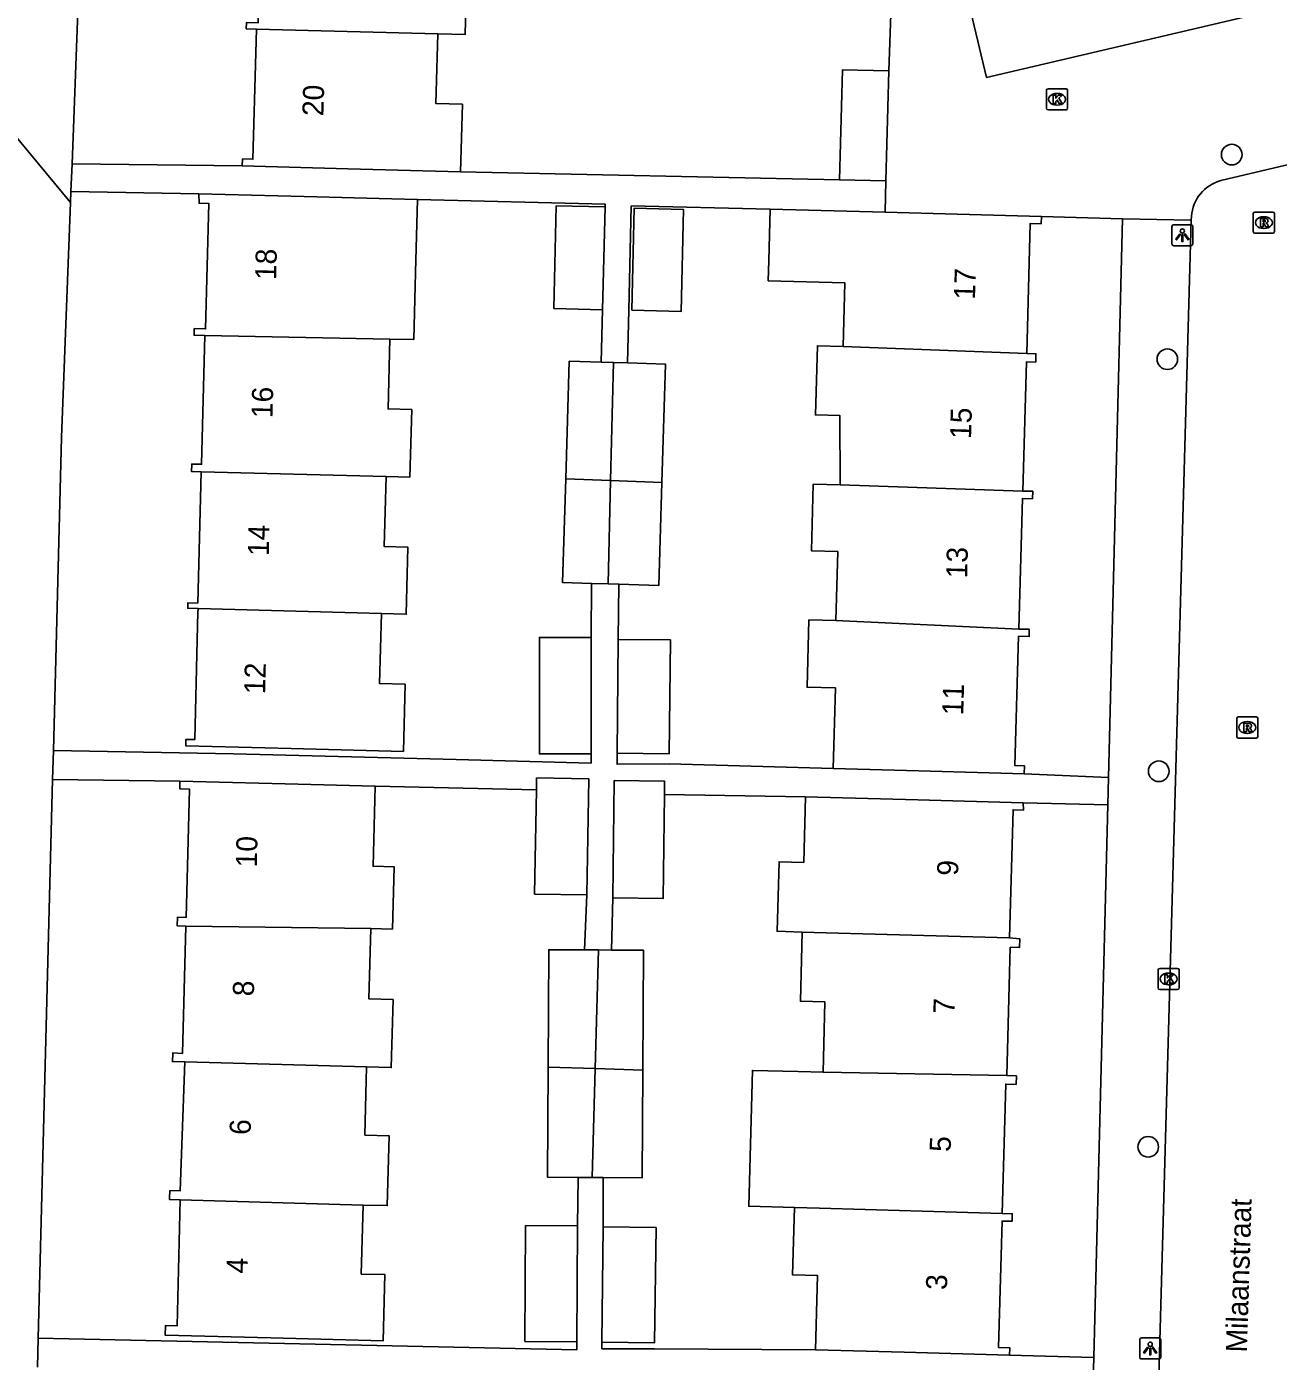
# Model space of a CAD drawing. Extents: x 162082 to 163393, y 388091 to 388632.
# Drawn here: x 162919.7 to 162979.1, y 388129.3 to 388192.6 of the extents above; entities that cross this region are included whole.
import ezdxf

# ---------------------------------------------------------------- set-up
doc = ezdxf.new("R2010")
doc.units = 0
for name, color, linetype in [('IMGEO_Boom', 7, 'Continuous'), ('IMGEO_Kolk', 7, 'Continuous'), ('IMGEO_Lichtpunt', 7, 'Continuous'), ('IMGEO_Openbare_ruimte_label', 7, 'Continuous'), ('IMGEO_Pand', 7, 'Continuous'), ('IMGEO_Pand_nummerreeks', 7, 'Continuous'), ('IMGEO_Rijbaan_lokaal_open', 7, 'Continuous'), ('IMGEO_Rioolput', 7, 'Continuous'), ('IMGEO_Voetpad_open', 7, 'Continuous')]:
    doc.layers.add(name, color=color, linetype=linetype)

msp = doc.modelspace()

# ---------------------------------------------------------------- linework, layer by layer
at = {"layer": 'IMGEO_Boom'}
for centre in [(162976.877, 388186.501), (162973.822, 388176.796), (162973.415, 388157.251), (162972.915, 388139.439)]:
    msp.add_circle(centre, 0.489, dxfattribs=at)
at = {"layer": 'IMGEO_Kolk'}
for p, q in [((162968.091, 388188.7), (162968.091, 388189.552)), ((162968.166, 388189.626), (162969.018, 388189.626)), ((162969.092, 388189.552), (162969.092, 388188.7)), ((162968.602, 388188.846), (162968.577, 388188.846)), ((162968.579, 388189.406), (162968.604, 388189.406)), ((162969.018, 388188.626), (162968.166, 388188.626)), ((162973.383, 388146.973), (162973.383, 388147.825)), ((162973.458, 388147.899), (162974.31, 388147.899)), ((162974.384, 388147.825), (162974.384, 388146.973)), ((162973.894, 388147.119), (162973.869, 388147.119)), ((162973.871, 388147.679), (162973.896, 388147.679)), ((162974.31, 388146.899), (162973.458, 388146.899))]:
    msp.add_line(p, q, dxfattribs=at)
for points in [[(162968.091, 388188.7), (162968.091, 388189.552)], [(162968.166, 388189.626), (162969.018, 388189.626)], [(162969.092, 388189.552), (162969.092, 388188.7)], [(162968.412, 388189.326), (162968.535, 388189.326), (162968.535, 388189.175), (162968.665, 388189.326), (162968.829, 388189.326), (162968.683, 388189.175), (162968.836, 388188.926), (162968.684, 388188.926), (162968.599, 388189.09), (162968.535, 388189.023), (162968.535, 388188.926), (162968.412, 388188.926), (162968.412, 388189.326)], [(162969.018, 388188.626), (162968.166, 388188.626)], [(162973.383, 388146.973), (162973.383, 388147.825)], [(162973.458, 388147.899), (162974.31, 388147.899)], [(162974.384, 388147.825), (162974.384, 388146.973)], [(162973.704, 388147.599), (162973.827, 388147.599), (162973.827, 388147.448), (162973.957, 388147.599), (162974.121, 388147.599), (162973.975, 388147.448), (162974.128, 388147.199), (162973.976, 388147.199), (162973.891, 388147.363), (162973.827, 388147.296), (162973.827, 388147.199), (162973.704, 388147.199), (162973.704, 388147.599)], [(162974.31, 388146.899), (162973.458, 388146.899)]]:
    msp.add_lwpolyline(points, dxfattribs=at)
for centre, start, end in [((162968.168, 388189.55), 91.55205, 178.44795), ((162968.168, 388189.55), 91.55205, 178.44795), ((162969.016, 388189.55), 1.55205, 88.44795), ((162969.016, 388189.55), 1.55205, 88.44795), ((162968.168, 388188.702), 181.55205, 268.44795), ((162968.168, 388188.702), 181.55205, 268.44795), ((162969.016, 388188.702), 271.55205, 358.44795), ((162969.016, 388188.702), 271.55205, 358.44795), ((162973.46, 388147.823), 91.55205, 178.44795), ((162973.46, 388147.823), 91.55205, 178.44795), ((162974.308, 388147.823), 1.55205, 88.44795), ((162974.308, 388147.823), 1.55205, 88.44795), ((162973.46, 388146.975), 181.55205, 268.44795), ((162973.46, 388146.975), 181.55205, 268.44795), ((162974.308, 388146.975), 271.55205, 358.44795), ((162974.308, 388146.975), 271.55205, 358.44795)]:
    msp.add_arc(centre, 0.0765, start, end, dxfattribs=at)
for centre, major_axis, ratio, start_param, end_param in [((162968.578, 388189.126), (-0.387, 0.002), 0.722429, 4.712389, 7.853982), ((162968.603, 388189.126), (-0.39, 0.002), 0.717154, 1.570796, 4.712389), ((162973.87, 388147.399), (-0.387, 0.002), 0.722429, 4.712389, 7.853982), ((162973.895, 388147.399), (-0.39, 0.002), 0.717154, 1.570796, 4.712389)]:
    msp.add_ellipse(centre, major_axis=major_axis, ratio=ratio, start_param=start_param, end_param=end_param, dxfattribs=at)
at = {"layer": 'IMGEO_Lichtpunt'}
for p, q in [((162974.938, 388183.177), (162974.13, 388183.177)), ((162974.938, 388183.177), (162974.13, 388183.177)), ((162974.036, 388183.082), (162974.036, 388182.275)), ((162974.036, 388183.082), (162974.036, 388182.275)), ((162975.032, 388182.275), (162975.032, 388183.082)), ((162975.032, 388182.275), (162975.032, 388183.082)), ((162974.13, 388182.181), (162974.938, 388182.181)), ((162974.13, 388182.181), (162974.938, 388182.181)), ((162972.511, 388130.275), (162972.511, 388129.468)), ((162972.511, 388130.275), (162972.511, 388129.468)), ((162973.413, 388130.37), (162972.605, 388130.37)), ((162973.413, 388130.37), (162972.605, 388130.37)), ((162973.507, 388129.468), (162973.507, 388130.275)), ((162973.507, 388129.468), (162973.507, 388130.275)), ((162972.605, 388129.374), (162973.413, 388129.374)), ((162972.605, 388129.374), (162973.413, 388129.374))]:
    msp.add_line(p, q, dxfattribs=at)
for points in [[(162974.41, 388182.746), (162974.449, 388182.718), (162974.261, 388182.456), (162974.223, 388182.483), (162974.41, 388182.746)], [(162974.512, 388182.698), (162974.559, 388182.698), (162974.559, 388182.376), (162974.512, 388182.376), (162974.512, 388182.698)], [(162974.622, 388182.718), (162974.66, 388182.745), (162974.847, 388182.483), (162974.808, 388182.455), (162974.622, 388182.718)], [(162972.885, 388129.939), (162972.924, 388129.911), (162972.736, 388129.649), (162972.698, 388129.676), (162972.885, 388129.939)], [(162972.987, 388129.891), (162973.034, 388129.891), (162973.034, 388129.569), (162972.987, 388129.569), (162972.987, 388129.891)], [(162973.097, 388129.911), (162973.135, 388129.938), (162973.322, 388129.676), (162973.283, 388129.648), (162973.097, 388129.911)]]:
    msp.add_lwpolyline(points, dxfattribs=at)
for centre in [(162974.535, 388182.88), (162973.01, 388130.073)]:
    msp.add_circle(centre, 0.0994, dxfattribs=at)
for centre, start, end in [((162974.13, 388183.082), 90, 180), ((162974.13, 388183.082), 90, 180), ((162974.938, 388183.082), 0, 90), ((162974.938, 388183.082), 0, 90), ((162974.13, 388182.275), 180, 270), ((162974.13, 388182.275), 180, 270), ((162974.938, 388182.275), 270, 0), ((162974.938, 388182.275), 270, 360), ((162972.605, 388130.275), 90, 180), ((162972.605, 388130.275), 90, 180), ((162973.413, 388130.275), 0, 90), ((162973.413, 388130.275), 0, 90), ((162972.605, 388129.468), 180, 270), ((162972.605, 388129.468), 180, 270), ((162973.413, 388129.468), 270, 0), ((162973.413, 388129.468), 270, 360)]:
    msp.add_arc(centre, 0.0946, start, end, dxfattribs=at)
at = {"layer": 'IMGEO_Pand'}
for points in [[(162930.625, 388192.454), (162930.137, 388192.468), (162930.145, 388192.767), (162930.711, 388192.752), (162930.879, 388198.904)], [(162939.348, 388198.681), (162939.259, 388195.428), (162940.603, 388195.392), (162940.516, 388192.195), (162939.221, 388192.23)], [(162929.952, 388185.968), (162929.961, 388186.297), (162930.456, 388186.283), (162930.625, 388192.454)], [(162939.221, 388192.23), (162930.625, 388192.454)], [(162939.221, 388192.23), (162939.13, 388188.925), (162940.388, 388188.891), (162940.3, 388185.684)], [(162958.276, 388185.312), (162958.42, 388190.53), (162960.619, 388190.469)], [(162960.619, 388190.469), (162960.475, 388185.252)], [(162929.952, 388185.968), (162934.951, 388185.831), (162940.3, 388185.684)], [(162958.276, 388185.312), (162960.475, 388185.252)], [(162928.181, 388177.916), (162927.665, 388177.93), (162927.673, 388178.25), (162928.213, 388178.236), (162928.369, 388184.179), (162927.902, 388184.191), (162927.892, 388184.644)], [(162938.256, 388184.372), (162937.039, 388184.404), (162932.891, 388184.513), (162927.892, 388184.644)], [(162938.256, 388184.372), (162938.165, 388180.911), (162938.082, 388177.726), (162936.956, 388177.755)], [(162947.038, 388179.14), (162944.726, 388179.195), (162944.843, 388184.079), (162947.154, 388184.024)], [(162947.038, 388179.14), (162947.154, 388184.024)], [(162948.419, 388179.121), (162948.534, 388183.953), (162950.88, 388183.897), (162950.765, 388179.066), (162948.419, 388179.121)], [(162958.448, 388177.401), (162958.531, 388180.416), (162954.896, 388180.516), (162954.922, 388181.481), (162954.989, 388183.92)], [(162960.434, 388183.77), (162954.989, 388183.92)], [(162960.434, 388183.77), (162967.851, 388183.566)], [(162967.851, 388183.566), (162967.841, 388183.222), (162967.321, 388183.237), (162967.152, 388177.071)], [(162928, 388171.451), (162927.546, 388171.463), (162927.555, 388171.824), (162928.021, 388171.812), (162928.181, 388177.916)], [(162936.956, 388177.755), (162928.181, 388177.916)], [(162936.956, 388177.755), (162936.869, 388174.435), (162937.987, 388174.406), (162937.903, 388171.209), (162936.772, 388171.239)], [(162958.3, 388170.839), (162958.296, 388174.125), (162957.134, 388174.157), (162957.225, 388177.435), (162958.448, 388177.401)], [(162958.448, 388177.401), (162967.152, 388177.071)], [(162967.152, 388177.071), (162967.59, 388177.059), (162967.579, 388176.659), (162967.142, 388176.671), (162966.973, 388170.545)], [(162945.288, 388171.117), (162945.456, 388176.701), (162946.972, 388176.655)], [(162947.55, 388176.638), (162946.972, 388176.655)], [(162947.419, 388171.037), (162947.55, 388176.638)], [(162948.22, 388176.618), (162947.55, 388176.638)], [(162948.22, 388176.618), (162950.021, 388176.564), (162949.851, 388170.945)], [(162927.853, 388164.971), (162927.364, 388164.985), (162927.371, 388165.244), (162927.837, 388165.232), (162928, 388171.451)], [(162936.772, 388171.239), (162928, 388171.451)], [(162936.772, 388171.239), (162936.685, 388167.91), (162937.807, 388167.88), (162937.724, 388164.699), (162936.548, 388164.73)], [(162946.52, 388166.162), (162945.139, 388166.203), (162945.288, 388171.117)], [(162947.419, 388171.037), (162945.288, 388171.117)], [(162947.419, 388171.037), (162947.305, 388166.138)], [(162949.851, 388170.945), (162947.419, 388171.037)], [(162949.851, 388170.945), (162949.704, 388166.065), (162947.807, 388166.123)], [(162958.099, 388164.397), (162958.189, 388167.674), (162956.939, 388167.708), (162957.026, 388170.874), (162958.3, 388170.839)], [(162958.3, 388170.839), (162966.973, 388170.545)], [(162966.973, 388170.545), (162967.435, 388170.532), (162967.426, 388170.177), (162966.949, 388170.19), (162966.779, 388163.998)], [(162947.305, 388166.138), (162946.52, 388166.162)], [(162947.305, 388166.138), (162947.807, 388166.123)], [(162936.548, 388164.73), (162936.461, 388161.414), (162937.674, 388161.382), (162937.591, 388158.193), (162932.266, 388158.332), (162927.267, 388158.463), (162927.275, 388158.765), (162927.693, 388158.754), (162927.849, 388164.809), (162927.852, 388164.919), (162927.853, 388164.971)], [(162927.853, 388164.971), (162936.548, 388164.73)], [(162957.973, 388157.381), (162958.078, 388161.202), (162956.734, 388161.239), (162956.822, 388164.433), (162958.099, 388164.397)], [(162966.779, 388163.998), (162958.099, 388164.397)], [(162946.496, 388158.072), (162944.039, 388158.072), (162944.039, 388163.6), (162946.496, 388163.6)], [(162946.496, 388163.6), (162946.496, 388158.072)], [(162966.779, 388163.998), (162967.272, 388163.985), (162967.272, 388163.644), (162966.765, 388163.658), (162966.596, 388157.523), (162967.042, 388157.511), (162967.032, 388157.131)], [(162947.725, 388158.109), (162947.781, 388163.507)], [(162947.781, 388163.507), (162950.255, 388163.482), (162950.2, 388158.084), (162947.725, 388158.109)], [(162967.032, 388157.131), (162962.034, 388157.269), (162957.973, 388157.381)], [(162927.273, 388149.906), (162926.866, 388149.916), (162926.879, 388150.324), (162927.287, 388150.309), (162927.447, 388156.41), (162926.984, 388156.422), (162926.993, 388156.788)], [(162926.993, 388156.788), (162931.992, 388156.657), (162936.257, 388156.545)], [(162936.257, 388156.545), (162936.157, 388152.746), (162937.147, 388152.72), (162937.07, 388149.765), (162936.047, 388149.791)], [(162943.899, 388156.363), (162943.909, 388156.937), (162946.385, 388156.895), (162946.292, 388151.385)], [(162949.972, 388156.148), (162949.98, 388156.774), (162947.595, 388156.806), (162947.52, 388151.241)], [(162943.899, 388156.363), (162943.816, 388151.427), (162946.292, 388151.385)], [(162949.972, 388156.148), (162949.905, 388151.209), (162947.52, 388151.241)], [(162956.664, 388156.039), (162956.578, 388152.925), (162955.407, 388152.957), (162955.316, 388149.659), (162956.508, 388149.625)], [(162966.986, 388155.755), (162961.988, 388155.893), (162956.664, 388156.039)], [(162966.335, 388149.352), (162966.502, 388155.428), (162967.006, 388155.414), (162966.986, 388155.755)], [(162927.273, 388149.906), (162927.114, 388143.868), (162926.655, 388143.89), (162926.653, 388143.848), (162926.635, 388143.483), (162927.23, 388143.466)], [(162936.047, 388149.791), (162927.273, 388149.906)], [(162935.848, 388143.227), (162937.017, 388143.196), (162937.102, 388146.423), (162935.96, 388146.453), (162936.047, 388149.791)], [(162957.493, 388142.972), (162957.585, 388146.311), (162956.417, 388146.343), (162956.508, 388149.625)], [(162956.508, 388149.625), (162957.642, 388149.593), (162966.335, 388149.352)], [(162966.335, 388149.352), (162966.826, 388149.304), (162966.815, 388148.894), (162966.374, 388148.906), (162966.206, 388142.816)], [(162944.457, 388143.219), (162944.486, 388148.788), (162946.18, 388148.779)], [(162946.18, 388148.779), (162946.852, 388148.776)], [(162946.691, 388143.15), (162946.852, 388148.776)], [(162946.852, 388148.776), (162947.461, 388148.773)], [(162947.461, 388148.773), (162948.972, 388148.765), (162948.943, 388143.081)], [(162927.23, 388143.466), (162927.002, 388137.346), (162926.52, 388137.361), (162926.504, 388137.001), (162926.501, 388136.931), (162927.012, 388136.917)], [(162927.23, 388143.466), (162935.848, 388143.227)], [(162935.679, 388136.677), (162936.828, 388136.647), (162936.915, 388139.966), (162935.763, 388139.996), (162935.848, 388143.227)], [(162945.885, 388137.984), (162944.43, 388137.992), (162944.457, 388143.219)], [(162946.691, 388143.15), (162944.457, 388143.219)], [(162946.542, 388137.981), (162946.691, 388143.15)], [(162946.691, 388143.15), (162948.943, 388143.081)], [(162948.943, 388143.081), (162948.916, 388137.969), (162947.073, 388137.978)], [(162957.493, 388142.972), (162956.311, 388143.004), (162954.147, 388143.063), (162953.97, 388136.615), (162956.134, 388136.557)], [(162966.206, 388142.816), (162957.493, 388142.972)], [(162965.991, 388136.279), (162966.16, 388142.41), (162966.651, 388142.396), (162966.662, 388142.803), (162966.206, 388142.816)], [(162945.885, 388137.984), (162946.542, 388137.981)], [(162947.073, 388137.978), (162946.542, 388137.981)], [(162935.679, 388136.677), (162935.593, 388133.404), (162936.714, 388133.375), (162936.632, 388130.231), (162931.297, 388130.371), (162926.298, 388130.502), (162926.31, 388130.97), (162926.856, 388130.946), (162927.012, 388136.917)], [(162927.012, 388136.917), (162935.679, 388136.677)], [(162957.138, 388129.81), (162957.235, 388133.328), (162956.046, 388133.361), (162956.134, 388136.557)], [(162956.134, 388136.557), (162957.323, 388136.525), (162965.991, 388136.279)], [(162945.809, 388130.19), (162943.351, 388130.207), (162943.388, 388135.698), (162945.846, 388135.682)], [(162945.846, 388135.682), (162945.809, 388130.19)], [(162965.991, 388136.279), (162966.468, 388136.266), (162966.458, 388135.906), (162965.985, 388135.919), (162965.82, 388129.919), (162966.351, 388129.905), (162966.341, 388129.556)], [(162946.999, 388130.17), (162947.073, 388135.642)], [(162947.073, 388135.642), (162949.572, 388135.608), (162949.497, 388130.136), (162946.999, 388130.17)], [(162957.138, 388129.81), (162961.343, 388129.694), (162966.341, 388129.556)]]:
    msp.add_lwpolyline(points, dxfattribs=at)
at = {"layer": 'IMGEO_Rijbaan_lokaal_open'}
for points in [[(162976.356, 388185.268), (162991.313, 388188.799)], [(162973.38, 388127.407), (162974.956, 388183.397)], [(162974.956, 388183.397), (162974.961, 388183.577)]]:
    msp.add_lwpolyline(points, dxfattribs=at)
msp.add_arc((162976.857, 388183.434), 1.901, 105.2709, 175.68686, dxfattribs=at)
at = {"layer": 'IMGEO_Rioolput'}
for p, q in [((162977.974, 388183.776), (162978.826, 388183.776)), ((162977.899, 388182.85), (162977.899, 388183.702)), ((162978.387, 388183.556), (162978.412, 388183.556)), ((162978.9, 388183.702), (162978.9, 388182.85)), ((162978.826, 388182.776), (162977.974, 388182.776)), ((162978.41, 388182.996), (162978.385, 388182.996)), ((162977.113, 388158.9), (162977.113, 388159.752)), ((162977.188, 388159.826), (162978.04, 388159.826)), ((162978.114, 388159.752), (162978.114, 388158.9)), ((162977.601, 388159.606), (162977.626, 388159.606)), ((162978.04, 388158.826), (162977.188, 388158.826)), ((162977.624, 388159.046), (162977.599, 388159.046))]:
    msp.add_line(p, q, dxfattribs=at)
for points in [[(162977.974, 388183.776), (162978.826, 388183.776)], [(162977.899, 388182.85), (162977.899, 388183.702)], [(162978.488, 388183.474), (162978.236, 388183.476), (162978.236, 388183.076)], [(162978.236, 388183.076), (162978.36, 388183.076), (162978.36, 388183.238), (162978.371, 388183.238)], [(162978.414, 388183.395), (162978.36, 388183.395), (162978.36, 388183.314)], [(162978.36, 388183.314), (162978.412, 388183.314)], [(162978.418, 388183.209), (162978.489, 388183.076), (162978.629, 388183.076), (162978.564, 388183.202)], [(162978.9, 388183.702), (162978.9, 388182.85)], [(162978.826, 388182.776), (162977.974, 388182.776)], [(162977.113, 388158.9), (162977.113, 388159.752)], [(162977.188, 388159.826), (162978.04, 388159.826)], [(162978.114, 388159.752), (162978.114, 388158.9)], [(162977.702, 388159.524), (162977.45, 388159.526), (162977.45, 388159.126)], [(162977.45, 388159.126), (162977.574, 388159.126), (162977.574, 388159.288), (162977.585, 388159.288)], [(162977.628, 388159.445), (162977.574, 388159.445), (162977.574, 388159.364)], [(162977.574, 388159.364), (162977.626, 388159.364)], [(162977.632, 388159.259), (162977.703, 388159.126), (162977.843, 388159.126), (162977.778, 388159.252)], [(162978.04, 388158.826), (162977.188, 388158.826)]]:
    msp.add_lwpolyline(points, dxfattribs=at)
for centre, radius, start, end in [((162977.976, 388183.7), 0.0765, 91.55205, 178.44795), ((162977.976, 388183.7), 0.0765, 91.55205, 178.44795), ((162978.824, 388183.7), 0.0765, 1.55205, 88.44795), ((162978.824, 388183.7), 0.0765, 1.55205, 88.44795), ((162978.37, 388183.185), 0.0533, 26.02933, 88.69889), ((162978.396, 388183.503), 0.19, 274.7715, 282.96867), ((162978.42, 388183.299), 0.0964, 77.00612, 93.18647), ((162978.434, 388183.356), 0.0378, 276.66336, 79.67722), ((162978.487, 388183.364), 0.109, 350.36119, 89.41601), ((162978.485, 388183.364), 0.112, 277.58423, 350.98172), ((162978.469, 388183.149), 0.108, 29.51342, 73.79051), ((162977.976, 388182.852), 0.0765, 181.55205, 268.44795), ((162977.976, 388182.852), 0.0765, 181.55205, 268.44795), ((162978.824, 388182.852), 0.0765, 271.55205, 358.44795), ((162978.824, 388182.852), 0.0765, 271.55205, 358.44795), ((162977.19, 388159.75), 0.0765, 91.55205, 178.44795), ((162977.19, 388159.75), 0.0765, 91.55205, 178.44795), ((162978.038, 388159.75), 0.0765, 1.55205, 88.44795), ((162978.038, 388159.75), 0.0765, 1.55205, 88.44795), ((162977.584, 388159.235), 0.0533, 26.02933, 88.69889), ((162977.61, 388159.553), 0.19, 274.7715, 282.96867), ((162977.634, 388159.349), 0.0964, 77.00612, 93.18647), ((162977.648, 388159.406), 0.0378, 276.66336, 79.67722), ((162977.701, 388159.414), 0.109, 350.36119, 89.41601), ((162977.699, 388159.414), 0.112, 277.58423, 350.98172), ((162977.683, 388159.199), 0.108, 29.51342, 73.79051), ((162977.19, 388158.902), 0.0765, 181.55205, 268.44795), ((162977.19, 388158.902), 0.0765, 181.55205, 268.44795), ((162978.038, 388158.902), 0.0765, 271.55205, 358.44795), ((162978.038, 388158.902), 0.0765, 271.55205, 358.44795)]:
    msp.add_arc(centre, radius, start, end, dxfattribs=at)
for centre, major_axis, ratio, start_param, end_param in [((162978.386, 388183.276), (-0.387, 0.002), 0.722429, 4.712389, 7.853982), ((162978.411, 388183.276), (-0.39, 0.002), 0.717154, 1.570796, 4.712389), ((162977.6, 388159.326), (-0.387, 0.002), 0.722429, 4.712389, 7.853982), ((162977.625, 388159.326), (-0.39, 0.002), 0.717154, 1.570796, 4.712389)]:
    msp.add_ellipse(centre, major_axis=major_axis, ratio=ratio, start_param=start_param, end_param=end_param, dxfattribs=at)
at = {"layer": 'IMGEO_Voetpad_open'}
for points in [[(162926.956, 388237.587), (162922.155, 388193.276), (162921.877, 388186.061)], [(162994.548, 388197.032), (162980.564, 388193.751), (162965.251, 388190.159), (162964.33, 388194.023)], [(162960.713, 388193.162), (162960.619, 388190.469)], [(162921.806, 388184.224), (162918.683, 388187.995), (162914.279, 388186.363)], [(162921.826, 388184.753), (162921.877, 388186.061)], [(162921.877, 388186.061), (162929.952, 388185.968)], [(162940.3, 388185.684), (162958.276, 388185.312)], [(162960.475, 388185.252), (162960.434, 388183.77)], [(162921.826, 388184.753), (162921.806, 388184.224)], [(162927.892, 388184.644), (162921.826, 388184.753)], [(162920.992, 388158.24), (162921.376, 388173.079), (162921.806, 388184.224)], [(162947.154, 388184.024), (162947.157, 388184.157), (162938.256, 388184.372)], [(162954.989, 388183.92), (162948.4, 388184.066), (162948.283, 388179.124), (162948.22, 388176.618)], [(162967.851, 388183.566), (162971.702, 388183.45)], [(162971.702, 388183.45), (162971.032, 388156.956)], [(162974.956, 388183.397), (162971.702, 388183.45)], [(162946.972, 388176.655), (162947.038, 388179.14)], [(162946.496, 388163.6), (162946.52, 388166.162)], [(162947.807, 388166.123), (162947.781, 388163.507)], [(162920.956, 388156.854), (162920.992, 388158.24)], [(162920.992, 388158.24), (162929.542, 388158.08), (162940.097, 388157.807), (162946.496, 388157.641), (162946.496, 388158.072)], [(162947.725, 388158.109), (162947.724, 388157.582), (162950.195, 388157.596), (162957.973, 388157.381)], [(162920.27, 388130.355), (162920.956, 388156.854)], [(162920.956, 388156.854), (162926.993, 388156.788)], [(162936.257, 388156.545), (162943.899, 388156.363)], [(162967.032, 388157.131), (162971.032, 388156.956)], [(162971.032, 388156.956), (162970.999, 388155.653)], [(162956.664, 388156.039), (162949.972, 388156.148)], [(162970.999, 388155.653), (162966.986, 388155.755)], [(162970.999, 388155.653), (162970.336, 388129.446)], [(162946.292, 388151.385), (162946.18, 388148.779)], [(162947.52, 388151.241), (162947.461, 388148.773)], [(162945.846, 388135.682), (162945.885, 388137.984)], [(162947.073, 388137.978), (162947.073, 388135.642)], [(162920.235, 388128.983), (162920.27, 388130.355)], [(162920.27, 388130.355), (162945.809, 388129.814), (162945.809, 388130.19)], [(162946.999, 388130.17), (162947.005, 388129.863), (162949.504, 388129.853), (162957.138, 388129.81)], [(162966.341, 388129.556), (162970.336, 388129.446)], [(162970.336, 388129.446), (162970.294, 388127.807)]]:
    msp.add_lwpolyline(points, dxfattribs=at)

# ---------------------------------------------------------------- texts
at = {"layer": 'IMGEO_Openbare_ruimte_label'}
msp.add_text('Milaanstraat', height=1, rotation=88.2244, dxfattribs=at).set_placement((162977.593, 388129.674))
at = {"layer": 'IMGEO_Pand_nummerreeks'}
for s, rotation, p in [('20', 88.35401, (162933.796, 388188.315)), ('18', 88.47698, (162931.554, 388180.54)), ('17', 88.38447, (162964.698, 388179.611)), ('16', 88.47698, (162931.38, 388173.992)), ('15', 88.38499, (162964.511, 388173.002)), ('14', 88.47614, (162931.206, 388167.448)), ('13', 88.38499, (162964.325, 388166.393)), ('12', 88.47614, (162931.032, 388160.9)), ('11', 88.38499, (162964.142, 388159.898)), ('10', 88.67045, (162930.641, 388152.682)), ('9', 88.47041, (162963.897, 388152.285)), ('8', 88.67095, (162930.499, 388146.571)), ('7', 88.46853, (162963.721, 388145.736)), ('6', 88.67095, (162930.346, 388139.994)), ('5', 88.47041, (162963.546, 388139.186)), ('4', 88.67045, (162930.194, 388133.422)), ('3', 88.46853, (162963.371, 388132.637))]:
    msp.add_text(s, height=1, rotation=rotation, dxfattribs=at).set_placement(p)

doc.saveas('drawing.dxf')
